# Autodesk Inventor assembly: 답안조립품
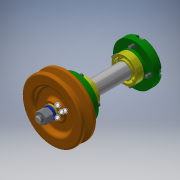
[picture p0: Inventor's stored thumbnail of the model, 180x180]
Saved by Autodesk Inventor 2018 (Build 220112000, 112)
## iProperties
Created: 2020-07
Part Number: 답안조립품
Material: 일반
Document SubType Name: Assembly
Designer: home
Author: home
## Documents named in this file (13)
- C:\Users\home\Desktop\700706V1036\답안조립품.iam
- C:\Users\home\Desktop\700706V1036\본체.ipt
- C:\Users\home\Desktop\700706V1036\베어링 6002.ipt
- C:\Users\home\Desktop\700706V1036\앞커버.ipt
- C:\Users\home\Desktop\700706V1036\뒤커버.ipt
- C:\Users\home\Desktop\700706V1036\오일 실 15 25 7.ipt
- C:\Users\home\Desktop\700706V1036\축.ipt
- C:\Users\home\Desktop\700706V1036\키 3x3x12.ipt
- C:\Users\home\Desktop\700706V1036\V벨트풀리.ipt
- C:\Users\home\Desktop\700706V1036\와셔 8x17.ipt
- C:\Users\home\Desktop\700706V1036\스프링와셔 8.ipt
- C:\Users\home\Desktop\700706V1036\너트 M8.ipt
- C:\Users\home\Desktop\700706V1036\볼트 M4x12.ipt
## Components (1 placed, 1 different names)
1. V벨트풀리:1
